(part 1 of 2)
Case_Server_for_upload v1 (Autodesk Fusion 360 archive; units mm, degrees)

design "Case_Server_for_upload" references "SSD1306_OLED_Display(128x64)", "DB_Updated", "Control"
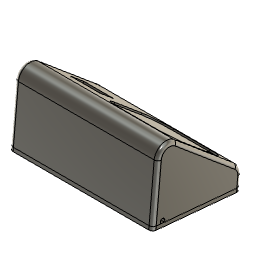
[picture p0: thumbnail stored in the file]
description: Part Number
part number: DB_Updated_PCB
external_derived "ExternalDerived1"
derived_instance "DerivedInstance1"
component_insert "Component Insert1"
sketch "Sketch1" plane through (0, 0, 0) normal (1, 0, 0) x axis (0, 1, 0)
  line L1 (0, 45.9198) -> (0, 0)
  line L2 (69.6996, 16.7708) -> (15.6902, 54.1431)
  line L3 (74.0094, 0) -> (74.0094, 8.5476)
  line L4 (0, 0) -> (74.0094, 0)
  line L5 (0, 4) -> (4, 4)
  line L6 (70.0094, 0) -> (70.0094, 4)
  line L7 (4, 0) -> (4, 4)
  line L8 (4, 45.9198) -> (4, 4)
  line L9 (67.4235, 13.4815) -> (13.4141, 50.8538)
  line L10 (70.0094, 4) -> (70.0094, 8.5476)
  line L11 (4, 4) -> (70.0094, 4)
  arc A1 centre (10, 45.9198) radius 10 clockwise from (0, 45.9198) to (15.6902, 54.1431)
  arc A2 centre (64.0094, 8.5476) radius 10 clockwise from (69.6996, 16.7708) to (74.0094, 8.5476)
  arc A3 centre (10, 45.9198) radius 6 clockwise from (4, 45.9198) to (13.4141, 50.8538)
  arc A4 centre (64.0094, 8.5476) radius 6 clockwise from (67.4235, 13.4815) to (70.0094, 8.5476)
  point P1 (0, 0)
  point P2 (0, 0)
  point P6 (0, 0)
  point P3 (0, 65)
  point P4 (74.0094, 13.7886)
  point P18 (0, 4)
  point P19 (70.0094, 0)
  point P20 (4, 0)
  coincident P1 P2
  vertical L1
  vertical L3
  coincident P1 P6
  perpendicular L1 L4
  coincident P3 L1
  coincident P3 L2
  tangent L1 A1
  tangent L2 A1
  coincident P4 L2
  coincident P4 L3
  tangent L2 A2
  tangent L3 A2
  equal A1 A2
  coincident L1 P18
  perpendicular L1 L5
  coincident L4 P19
  perpendicular L4 L6
  coincident L4 P20
  perpendicular L4 L7
  dimension "d1" distance P2 P3 = 65
  dimension "d2" distance P3 P4 = 90
  dimension "d3" radius A1 = 10
  dimension "d4" = 4
extrude "Extrude1" new body sketch "Sketch1" along normal blind 120
move "Move1"
shell "Shell1" innerThickness 5
fillet "Fillet1" radius 3
fillet "Fillet2" radius 3
sketch "Sketch2" plane through (0, 0, 0) normal (-1, 0, 0) x axis (0, -1, 0)
  line L1 (-3, 45.9198) -> (-3, 0)
  line L2 (-67.9925, 14.3039) -> (-13.9831, 51.6761)
  line L3 (-71.0094, 0) -> (-71.0094, 8.5476)
  line L4 (-3, 0) -> (-71.0094, 0)
  arc A1 centre (-10, 45.9198) radius 7 clockwise from (-13.9831, 51.6761) to (-3, 45.9198)
  arc A2 centre (-64.0094, 8.5476) radius 7 clockwise from (-71.0094, 8.5476) to (-67.9925, 14.3039)
  circle C1 centre (-9.0686, 10.0646) radius 3.15
  dimension "d12" diameter C1 = 6.3
extrude "Extrude2" cut sketch "Sketch2" profile of C1 against normal blind 5
sketch "Sketch3" plane through (120, 0, 0) normal (1, 0, 0) x axis (0, 1, 0)
  line L1 (71.0094, 8.5476) -> (71.0094, 0)
  line L2 (13.9831, 51.6761) -> (67.9925, 14.3039)
  line L3 (3, 0) -> (3, 45.9198)
  line L4 (71.0094, 0) -> (3, 0)
  line L5 (6.5581, 1.8971) -> (6.5581, 0)
  line L6 (6.5581, 0) -> (6.5581, 1.8971)
  line L7 (10.0566, 0) -> (10.0566, 1.8226)
  arc A1 centre (64.0094, 8.5476) radius 7 clockwise from (67.9925, 14.3039) to (71.0094, 8.5476)
  arc A2 centre (10, 45.9198) radius 7 clockwise from (3, 45.9198) to (13.9831, 51.6761)
  circle C1 centre (8.3081, 1.75) radius 1.75
  point P10 (6.5581, 0)
  point P13 (10.0566, 1.8226)
  point P14 (10.0566, 0)
  coincident L4 P10
  perpendicular L4 L5
  tangent L5 C1
  tangent L4 C1
  coincident C1 P13
  coincident L4 P14
  perpendicular L4 L7
  dimension "d16" radius C1 = 1.75
extrude "Extrude3" cut sketch "Sketch3" profile of L4 C1 L6 L7 against normal blind 5
sketch "Sketch4" plane through (0, 30.4146, 43.9544) normal (0, 0.569, 0.8223) x axis (-1, 0, 0)
  line L1 (-117, -47.773) -> (-117, 17.9058)
  line L2 (-3, -47.773) -> (-117, -47.773)
  line L3 (-3, 17.9058) -> (-3, -47.773)
  line L4 (-117, 17.9058) -> (-3, 17.9058)
  line L5 (-113.9567, 15.0558) -> (-113.9567, 17.9058)
  line L6 (-68.7567, 15.0558) -> (-98.9567, 15.0558)
  line L7 (-53.7567, -30.1442) -> (-53.7567, 0.0558)
  line L8 (-98.9567, -45.1442) -> (-68.7567, -45.1442)
  line L9 (-113.9567, 0.0558) -> (-113.9567, -30.1442)
  arc A1 centre (-68.7567, -30.1442) radius 15 clockwise from (-53.7567, -30.1442) to (-68.7567, -45.1442)
  arc A2 centre (-68.7567, 0.0558) radius 15 clockwise from (-68.7567, 15.0558) to (-53.7567, 0.0558)
  arc A3 centre (-98.9567, 0.0558) radius 15 clockwise from (-113.9567, 0.0558) to (-98.9567, 15.0558)
  arc A4 centre (-98.9567, -30.1442) radius 15 clockwise from (-98.9567, -45.1442) to (-113.9567, -30.1442)
  point P6 (-113.9567, 17.9058)
  point P8 (-53.7567, 15.0558)
  point P7 (-113.9567, 15.0558)
  point P9 (-113.9567, -45.1442)
  coincident L4 P6
  perpendicular L4 L5
  horizontal L6
  vertical L7
  horizontal L8
  vertical L9
  tangent L7 A1
  tangent L8 A1
  coincident P8 L6
  coincident P8 L7
  tangent L6 A2
  tangent L7 A2
  coincident P7 L9
  coincident P7 L6
  tangent L9 A3
  tangent L6 A3
  coincident P9 L9
  coincident P9 L8
  tangent L9 A4
  tangent L8 A4
  dimension "d19" distance P6 P7 = 2.85
  dimension "d20" distance P7 P8 = 60.2
  dimension "d21" distance P7 P9 = 60.2
  dimension "d22" radius A1 = 15
  dimension "d23" radius A2 = 15
  dimension "d24" radius A3 = 15
  dimension "d25" radius A4 = 15
extrude "Extrude4" cut sketch "Sketch4" profile of L6 L7 L8 L9 A1 A2 A3 A4 against normal blind 1.2
sketch "Sketch5" plane through (0, 30.4146, 43.9544) normal (0, 0.569, 0.8223) x axis (-1, 0, 0)
  line L1 (-113.9567, 0.0558) -> (-113.9567, -30.1442)
  line L2 (-68.7567, 15.0558) -> (-98.9567, 15.0558)
  line L3 (-53.7567, -30.1442) -> (-53.7567, 0.0558)
  line L4 (-98.9567, -45.1442) -> (-68.7567, -45.1442)
  line L5 (-117, -47.773) -> (-117, 17.9058)
  line L6 (-3, -47.773) -> (-117, -47.773)
  line L7 (-3, 17.9058) -> (-3, -47.773)
  line L8 (-117, 17.9058) -> (-3, 17.9058)
  line L9 (-3, -12.826) -> (-53.7567, -12.826)
  line L10 (-28.9783, -47.773) -> (-28.9783, 17.9058)
  line L11 (-40.7783, -21.176) -> (-15.9783, -21.176)
  line L12 (-40.7783, -4.476) -> (-40.7783, -21.176)
  line L13 (-15.9783, -4.476) -> (-40.7783, -4.476)
  line L14 (-15.9783, -21.176) -> (-15.9783, -4.476)
  line L15 (-40.7783, -4.476) -> (-15.9783, -21.176)
  line L16 (-15.9783, -4.476) -> (-40.7783, -21.176)
  line L17 (-41.4783, -25.926) -> (-15.2783, -25.926)
  line L18 (-41.4783, 0.274) -> (-41.4783, -25.926)
  line L19 (-15.2783, 0.274) -> (-41.4783, 0.274)
  line L20 (-15.2783, -25.926) -> (-15.2783, 0.274)
  line L21 (-41.4783, 0.274) -> (-15.2783, -25.926)
  line L22 (-15.2783, 0.274) -> (-41.4783, -25.926)
  arc A1 centre (-98.9567, 0.0558) radius 15 clockwise from (-113.9567, 0.0558) to (-98.9567, 15.0558)
  arc A2 centre (-68.7567, 0.0558) radius 15 clockwise from (-68.7567, 15.0558) to (-53.7567, 0.0558)
  arc A3 centre (-68.7567, -30.1442) radius 15 clockwise from (-53.7567, -30.1442) to (-68.7567, -45.1442)
  arc A4 centre (-98.9567, -30.1442) radius 15 clockwise from (-98.9567, -45.1442) to (-113.9567, -30.1442)
  point P18 (-53.7567, -12.826)
  point P19 (-3, -12.826)
  point P20 (-28.9783, 17.9058)
  point P21 (-28.9783, -47.773)
  point P26 (-28.3783, -12.826)
  point P31 (-28.3783, -12.826)
  point P24 (-40.7783, -4.476)
  point P25 (-15.9783, -4.476)
  point P23 (-40.7783, -21.176)
  point P29 (-41.4783, 0.274)
  point P30 (-15.2783, 0.274)
  point P28 (-41.4783, -25.926)
  coincident L3 P18
  coincident L7 P19
  perpendicular L7 L9
  coincident L8 P20
  coincident L6 P21
  perpendicular L6 L10
  horizontal L11
  perpendicular L11 L12
  parallel L11 L13
  parallel L12 L14
  coincident L15 P26
  coincident L16 P26
  midpoint L9 P26
  horizontal L17
  perpendicular L17 L18
  parallel L17 L19
  parallel L18 L20
  coincident L21 P31
  coincident L22 P31
  coincident P26 P31
  dimension "d28" distance P24 P25 = 24.8
  dimension "d29" distance P23 P24 = 16.7
  dimension "d30" distance P29 P30 = 26.2
  dimension "d31" distance P28 P29 = 26.2
sketch "Sketch6" plane through (0, 30.4146, 43.9544) normal (0, 0.569, 0.8223) x axis (-1, 0, 0)
  line L1 (-117, -47.773) -> (-117, 17.9058)
  line L2 (-3, -47.773) -> (-117, -47.773)
  line L3 (-3, 17.9058) -> (-3, -47.773)
  line L4 (-117, 17.9058) -> (-3, 17.9058)
  line L5 (-113.9567, 0.0558) -> (-113.9567, -30.1442)
  line L6 (-68.7567, 15.0558) -> (-98.9567, 15.0558)
  line L7 (-53.7567, -30.1442) -> (-53.7567, 0.0558)
  line L8 (-98.9567, -45.1442) -> (-68.7567, -45.1442)
  line L9 (-51.5262, 17.9058) -> (-117, 17.9058)
  line L10 (-51.5262, -47.773) -> (-51.5262, 17.9058)
  line L11 (-117, -47.773) -> (-51.5262, -47.773)
  line L12 (-117, 17.9058) -> (-117, -47.773)
  line L13 (-11.096, 0.5418) -> (-45.2906, 0.5418)
  line L14 (-11.096, -26.3669) -> (-11.096, 0.5418)
  line L15 (-45.2906, -26.3669) -> (-11.096, -26.3669)
  line L16 (-45.2906, 0.5418) -> (-45.2906, -26.3669)
  line L17 (-51.5262, 17.9058) -> (-117, 17.9058)
  line L18 (-51.5262, -47.773) -> (-51.5262, 17.9058)
  line L19 (-117, -47.773) -> (-51.5262, -47.773)
  line L20 (-117, 17.9058) -> (-117, -47.773)
  arc A1 centre (-98.9567, 0.0558) radius 15 clockwise from (-113.9567, 0.0558) to (-98.9567, 15.0558)
  arc A2 centre (-68.7567, 0.0558) radius 15 clockwise from (-68.7567, 15.0558) to (-53.7567, 0.0558)
  arc A3 centre (-68.7567, -30.1442) radius 15 clockwise from (-53.7567, -30.1442) to (-68.7567, -45.1442)
  arc A4 centre (-98.9567, -30.1442) radius 15 clockwise from (-98.9567, -45.1442) to (-113.9567, -30.1442)
  point P20 (-51.5262, -47.773)
  point P2 (-117, 17.9058)
  point P18 (-117, 17.9058)
  horizontal L9
  vertical L10
  horizontal L11
  vertical L12
  coincident L2 P20
  coincident P2 P18
  horizontal L13
  vertical L14
  horizontal L15
  vertical L16
  horizontal L17
  vertical L18
  horizontal L19
  vertical L20
sketch "Sketch7" plane through (0, 0, 0) normal (0, 0, 1) x axis (1, 0, 0)
  line L1 (-65.2, -35) -> (-35, -35)
  line L2 (-80.2, 10.2) -> (-80.2, -20)
  line L3 (-35, 25.2) -> (-65.2, 25.2)
  line L4 (-20, -20) -> (-20, 10.2)
  line L5 (-83.2, 10.2) -> (-83.2, -20)
  line L6 (-65.2, -38) -> (-35, -38)
  line L7 (-17, -20) -> (-17, 10.2)
  line L8 (-35, 28.2) -> (-65.2, 28.2)
  arc A1 centre (-35, -20) radius 15 clockwise from (-20, -20) to (-35, -35)
  arc A2 centre (-35, 10.2) radius 15 clockwise from (-35, 25.2) to (-20, 10.2)
  arc A3 centre (-65.2, -20) radius 15 clockwise from (-65.2, -35) to (-80.2, -20)
  arc A4 centre (-65.2, 10.2) radius 15 clockwise from (-80.2, 10.2) to (-65.2, 25.2)
  arc A5 centre (-65.2, 10.2) radius 18 clockwise from (-83.2, 10.2) to (-65.2, 28.2)
  arc A6 centre (-65.2, -20) radius 18 clockwise from (-65.2, -38) to (-83.2, -20)
  arc A7 centre (-35, -20) radius 18 clockwise from (-17, -20) to (-35, -38)
  arc A8 centre (-35, 10.2) radius 18 clockwise from (-35, 28.2) to (-17, 10.2)
  point P2 (-20, -35)
  point P4 (-20, 25.2)
  point P3 (-80.2, -35)
  horizontal L1
  vertical L2
  horizontal L3
  vertical L4
  coincident P2 L4
  coincident P2 L1
  tangent L4 A1
  tangent L1 A1
  coincident P4 L4
  coincident P4 L3
  tangent L4 A2
  tangent L3 A2
  coincident P3 L2
  coincident P3 L1
  tangent L2 A3
  tangent L1 A3
  tangent L2 A4
  tangent L3 A4
  dimension "d45" distance P2 P3 = 60.2
  dimension "d46" distance P2 P4 = 60.2
  dimension "d47" radius A1 = 15
  dimension "d48" radius A2 = 15
  dimension "d49" radius A3 = 15
  dimension "d50" radius A4 = 15
  dimension "d51" = -3
extrude "Extrude9" new body sketch "Sketch7" against normal blind 5
extrude "Extrude10" cut sketch "Sketch7" profile of L1 L2 L3 L4 A1 A2 A3 A4 against normal blind 1.3
sketch "Sketch8" plane through (0, 0, 0) normal (0, 0, -1) x axis (1, 0, 0)
  line L1 (120, -6.5581) -> (115, -6.5581)
  line L2 (120, -3) -> (120, -6.5581)
  line L3 (3, 0) -> (117, 0)
  line L4 (0, -71.0094) -> (0, -3)
  line L5 (117, -74.0094) -> (3, -74.0094)
  line L6 (120, -10.0566) -> (120, -71.0094)
  line L7 (115, -10.0566) -> (120, -10.0566)
  line L8 (115, -69.0094) -> (115, -10.0566)
  line L9 (5, -69.0094) -> (115, -69.0094)
  line L10 (5, -5) -> (5, -69.0094)
  line L11 (115, -5) -> (5, -5)
  line L12 (115, -6.5581) -> (115, -5)
  line L13 (115, -10.0566) -> (115, -6.5581)
  line L14 (120, -10.0566) -> (120, -6.5581)
  arc A1 centre (117, -3) radius 3 clockwise from (117, 0) to (120, -3)
  arc A2 centre (3, -3) radius 3 clockwise from (0, -3) to (3, 0)
  arc A3 centre (3, -71.0094) radius 3 clockwise from (3, -74.0094) to (0, -71.0094)
  arc A4 centre (117, -71.0094) radius 3 clockwise from (120, -71.0094) to (117, -74.0094)
  circle C1 centre (3, -3) radius 1.4
  circle C2 centre (117, -3) radius 1.4
  circle C3 centre (117, -71.0094) radius 1.4
  circle C4 centre (3, -71.0094) radius 1.4
  point P2 (115, -6.5581)
  point P22 (115, -6.5581)
  point P17 (115, -10.0566)
  point P23 (115, -10.0566)
  point P3 (120, -6.5581)
  point P24 (120, -6.5581)
  point P16 (120, -10.0566)
  point P25 (120, -10.0566)
  coincident P2 P22
  coincident P17 P23
  coincident P3 P24
  coincident P16 P25
  concentric A2 C1
  concentric A1 C2
  concentric A4 C3
  concentric A3 C4
  dimension "d59" diameter C1 = 2.8
  dimension "d99" diameter C2 = 2.8
  dimension "d100" diameter C3 = 2.8
  dimension "d101" diameter C4 = 2.8
move "Move2"
position "Position1"
sketch "Sketch1" plane through (0, 21.8322, 26.0187) normal (0, -0.6428, -0.766) x axis (1, 0, 0)
  line L1 (5, -47.773) -> (5, 17.9058)
  line L2 (115, -47.773) -> (5, -47.773)
  line L3 (115, 17.9058) -> (115, -47.773)
  line L4 (5, 17.9058) -> (115, 17.9058)
  line L5 (40.7783, -12.826) -> (15.9783, -12.826)
  line L6 (28.3783, -21.176) -> (28.3783, -12.826)
  point P8 (28.3783, -12.826)
  point P10 (28.3783, -12.826)
  point P11 (30.7776, -12.826)
  midpoint L5 P8
  coincident P8 P10
  coincident L5 P11
move "Move3"
move "Move4"
position "Position2"
sketch "Sketch2" plane through (0, 26.1389, 31.1512) normal (0, 0.6428, 0.766) x axis (-1, 0, 0)
  line L1 (-113.9567, 0.0558) -> (-113.9567, -30.1442)
  line L2 (-68.7567, 15.0558) -> (-98.9567, 15.0558)
  line L3 (-53.7567, -30.1442) -> (-53.7567, 0.0558)
  line L4 (-98.9567, -45.1442) -> (-68.7567, -45.1442)
  line L5 (-117, -47.773) -> (-117, 17.9058)
  line L6 (-3, -47.773) -> (-117, -47.773)
  line L7 (-3, 17.9058) -> (-3, -47.773)
  line L8 (-117, 17.9058) -> (-3, 17.9058)
  arc A1 centre (-98.9567, 0.0558) radius 15 clockwise from (-113.9567, 0.0558) to (-98.9567, 15.0558)
  arc A2 centre (-68.7567, 0.0558) radius 15 clockwise from (-68.7567, 15.0558) to (-53.7567, 0.0558)
  arc A3 centre (-68.7567, -30.1442) radius 15 clockwise from (-53.7567, -30.1442) to (-68.7567, -45.1442)
  arc A4 centre (-98.9567, -30.1442) radius 15 clockwise from (-98.9567, -45.1442) to (-113.9567, -30.1442)
move "Move5"
component_insert "Component Insert2"
position "Position3"
sketch "Sketch10" plane through (0, 30.4146, 43.9544) normal (0, 0.569, 0.8223) x axis (-1, 0, 0)
  line L1 (-113.9567, 0.0558) -> (-113.9567, -30.1442)
  line L2 (-68.7567, 15.0558) -> (-98.9567, 15.0558)
  line L3 (-53.7567, -30.1442) -> (-53.7567, 0.0558)
  line L4 (-98.9567, -45.1442) -> (-68.7567, -45.1442)
  line L5 (-117, -47.773) -> (-117, 17.9058)
  line L6 (-3, -47.773) -> (-117, -47.773)
  line L7 (-3, 17.9058) -> (-3, -47.773)
  line L8 (-117, 17.9058) -> (-3, 17.9058)
  line L9 (-30.6726, -2.6578) -> (-30.6726, -2.7517)
  line L10 (-30.3337, -2.6573) -> (-30.6726, -2.6578)
  line L11 (-30.3337, -2.9542) -> (-30.3337, -2.6573)
  curve K1 (-30.4947, -3.0478) -> (-30.3337, -2.9542)
  curve K2 (-30.6649, -3.0791) -> (-30.4947, -3.0478)
  curve K3 (-30.8791, -3.0287) -> (-30.6649, -3.0791)
  curve K4 (-31.0246, -2.8827) -> (-30.8791, -3.0287)
  curve K5 (-31.0737, -2.6693) -> (-31.0246, -2.8827)
  curve K6 (-31.0248, -2.4513) -> (-31.0737, -2.6693)
  curve K7 (-30.8843, -2.301) -> (-31.0248, -2.4513)
  curve K8 (-30.6731, -2.2518) -> (-30.8843, -2.301)
  curve K9 (-30.5162, -2.2799) -> (-30.6731, -2.2518)
  curve K10 (-30.4063, -2.3583) -> (-30.5162, -2.2799)
  curve K11 (-30.3457, -2.4892) -> (-30.4063, -2.3583)
  line L12 (-30.4412, -2.5154) -> (-30.3457, -2.4892)
  curve K12 (-30.4859, -2.4194) -> (-30.4412, -2.5154)
  curve K13 (-30.5623, -2.3634) -> (-30.4859, -2.4194)
  curve K14 (-30.6726, -2.3424) -> (-30.5623, -2.3634)
  curve K15 (-30.7981, -2.3645) -> (-30.6726, -2.3424)
  curve K16 (-30.8835, -2.4226) -> (-30.7981, -2.3645)
  curve K17 (-30.934, -2.5018) -> (-30.8835, -2.4226)
  curve K18 (-30.9645, -2.6628) -> (-30.934, -2.5018)
  curve K19 (-30.9277, -2.8417) -> (-30.9645, -2.6628)
  curve K20 (-30.8205, -2.9487) -> (-30.9277, -2.8417)
  curve K21 (-30.6709, -2.9836) -> (-30.8205, -2.9487)
  curve K22 (-30.5367, -2.9572) -> (-30.6709, -2.9836)
  curve K23 (-30.4374, -2.9007) -> (-30.5367, -2.9572)
  line L13 (-30.4374, -2.7517) -> (-30.4374, -2.9007)
  line L14 (-30.6726, -2.7517) -> (-30.4374, -2.7517)
  line L15 (-21.3678, -2.2655) -> (-21.675, -3.0655)
  line L16 (-21.2538, -2.2655) -> (-21.3678, -2.2655)
  line L17 (-20.9263, -3.0655) -> (-21.2538, -2.2655)
  line L18 (-21.0469, -3.0655) -> (-20.9263, -3.0655)
  line L19 (-21.1402, -2.8232) -> (-21.0469, -3.0655)
  line L20 (-21.4748, -2.8232) -> (-21.1402, -2.8232)
  line L21 (-21.5626, -3.0655) -> (-21.4748, -2.8232)
  line L22 (-21.675, -3.0655) -> (-21.5626, -3.0655)
  line L23 (-24.1607, -2.8117) -> (-24.2666, -2.785)
  curve K24 (-24.2805, -3.0106) -> (-24.1607, -2.8117)
  curve K25 (-24.492, -3.0791) -> (-24.2805, -3.0106)
  curve K26 (-24.7023, -3.0265) -> (-24.492, -3.0791)
  curve K27 (-24.8256, -2.8739) -> (-24.7023, -3.0265)
  curve K28 (-24.8679, -2.6595) -> (-24.8256, -2.8739)
  curve K29 (-24.8202, -2.4415) -> (-24.8679, -2.6595)
  curve K30 (-24.6843, -2.3001) -> (-24.8202, -2.4415)
  curve K31 (-24.4903, -2.2518) -> (-24.6843, -2.3001)
  curve K32 (-24.2884, -2.313) -> (-24.4903, -2.2518)
  curve K33 (-24.1744, -2.4849) -> (-24.2884, -2.313)
  line L24 (-24.2786, -2.5094) -> (-24.1744, -2.4849)
  curve K34 (-24.3593, -2.3823) -> (-24.2786, -2.5094)
  curve K35 (-24.4925, -2.3424) -> (-24.3593, -2.3823)
  curve K36 (-24.6467, -2.3866) -> (-24.4925, -2.3424)
  curve K37 (-24.7337, -2.5053) -> (-24.6467, -2.3866)
  curve K38 (-24.7588, -2.6589) -> (-24.7337, -2.5053)
  curve K39 (-24.7291, -2.8371) -> (-24.7588, -2.6589)
  curve K40 (-24.6366, -2.9509) -> (-24.7291, -2.8371)
  curve K41 (-24.5007, -2.9885) -> (-24.6366, -2.9509)
  curve K42 (-24.3501, -2.9372) -> (-24.5007, -2.9885)
  curve K43 (-24.2666, -2.785) -> (-24.3501, -2.9372)
  line L25 (-23.0759, -2.7997) -> (-23.1757, -2.8085)
  curve K44 (-23.0428, -2.8982) -> (-23.0759, -2.7997)
  curve K45 (-22.9623, -2.9604) -> (-23.0428, -2.8982)
  curve K46 (-22.8396, -2.9842) -> (-22.9623, -2.9604)
  curve K47 (-22.7326, -2.9662) -> (-22.8396, -2.9842)
  curve K48 (-22.6636, -2.9168) -> (-22.7326, -2.9662)
  curve K49 (-22.6409, -2.8483) -> (-22.6636, -2.9168)
  curve K50 (-22.6628, -2.7825) -> (-22.6409, -2.8483)
  curve K51 (-22.7348, -2.7353) -> (-22.6628, -2.7825)
  curve K52 (-22.8772, -2.6963) -> (-22.7348, -2.7353)
  curve K53 (-23.0317, -2.6464) -> (-22.8772, -2.6963)
  curve K54 (-23.1171, -2.5719) -> (-23.0317, -2.6464)
  curve K55 (-23.1452, -2.4723) -> (-23.1171, -2.5719)
  curve K56 (-23.1108, -2.3591) -> (-23.1452, -2.4723)
  curve K57 (-23.0104, -2.2791) -> (-23.1108, -2.3591)
  curve K58 (-22.8636, -2.2518) -> (-23.0104, -2.2791)
  curve K59 (-22.7067, -2.2805) -> (-22.8636, -2.2518)
  curve K60 (-22.6022, -2.3648) -> (-22.7067, -2.2805)
  curve K61 (-22.5629, -2.4909) -> (-22.6022, -2.3648)
  line L26 (-22.6644, -2.4985) -> (-22.5629, -2.4909)
  curve K62 (-22.7198, -2.3839) -> (-22.6644, -2.4985)
  curve K63 (-22.8592, -2.3452) -> (-22.7198, -2.3839)
  curve K64 (-22.9992, -2.3804) -> (-22.8592, -2.3452)
  curve K65 (-23.0431, -2.4652) -> (-22.9992, -2.3804)
  curve K66 (-23.012, -2.5362) -> (-23.0431, -2.4652)
  curve K67 (-22.8524, -2.5932) -> (-23.012, -2.5362)
  curve K68 (-22.6753, -2.6442) -> (-22.8524, -2.5932)
  curve K69 (-22.5722, -2.7258) -> (-22.6753, -2.6442)
  curve K70 (-22.5389, -2.8396) -> (-22.5722, -2.7258)
  curve K71 (-22.5754, -2.9599) -> (-22.5389, -2.8396)
  curve K72 (-22.6805, -3.0478) -> (-22.5754, -2.9599)
  curve K73 (-22.8347, -3.0791) -> (-22.6805, -3.0478)
  curve K74 (-23.0166, -3.0475) -> (-22.8347, -3.0791)
  curve K75 (-23.1318, -2.9523) -> (-23.0166, -3.0475)
  curve K76 (-23.1757, -2.8085) -> (-23.1318, -2.9523)
  line L27 (-33.3, -25.8655) -> (-38.7, -25.8655)
  line L28 (-33.3, -24.3655) -> (-33.3, -25.8655)
  line L29 (-19.7, -23.3655) -> (-32.3, -23.3655)
  line L30 (-18.7, -25.8655) -> (-18.7, -24.3655)
  line L31 (-13.3, -25.8655) -> (-18.7, -25.8655)
  line L32 (-13.3, 0.3345) -> (-13.3, -25.8655)
  line L33 (-38.7, 0.3345) -> (-13.3, 0.3345)
  line L34 (-38.7, -25.8655) -> (-38.7, 0.3345)
  line L35 (-30.1787, -2.2655) -> (-30.1787, -3.0655)
  line L36 (-30.0701, -2.2655) -> (-30.1787, -2.2655)
  line L37 (-29.6499, -2.8936) -> (-30.0701, -2.2655)
  line L38 (-29.6499, -2.2655) -> (-29.6499, -2.8936)
  line L39 (-29.5484, -2.2655) -> (-29.6499, -2.2655)
  line L40 (-29.5484, -3.0655) -> (-29.5484, -2.2655)
  line L41 (-29.657, -3.0655) -> (-29.5484, -3.0655)
  line L42 (-30.0772, -2.4368) -> (-29.657, -3.0655)
  line L43 (-30.0772, -3.0655) -> (-30.0772, -2.4368)
  line L44 (-30.1787, -3.0655) -> (-30.0772, -3.0655)
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  point P261 (-13.65, -18.6655)
  point P270 (-13.65, -18.6655)
  point P263 (-38.35, -4.1655)
  point P268 (-38.35, -4.1655)
  point P121 (-13.3, -25.8655)
  point P274 (-13.3, -25.8655)
  point P123 (-38.7, 0.3345)
  point P272 (-38.7, 0.3345)
  coincident P261 P270
  coincident P263 P268
  coincident P121 P274
  coincident P123 P272
  dimension "d81" diameter = 1.5
  dimension "d82" diameter = 1.5
  dimension "d83" diameter = 1.5
  dimension "d84" diameter = 1.5
  dimension "d87" = -0.1
extrude "Extrude16" cut sketch "Sketch10" along a picked direction blind -7
extrude "Extrude17" cut sketch "Sketch10" along a picked direction blind 1 from offset -5
sketch "Sketch11" plane through (5, 0, 0) normal (1, 0, 0) x axis (0, 1, 0)
  line L1 (69.0094, 8.5476) -> (69.0094, 0)
  line L2 (12.8451, 50.0314) -> (66.8545, 12.6592)
  line L3 (5, 0) -> (5, 45.9198)
  line L4 (69.0094, 0) -> (5, 0)
  circle C1 centre (9.0686, 10.0646) radius 3.15
  arc A1 centre (64.0094, 8.5476) radius 5 clockwise from (66.8545, 12.6592) to (69.0094, 8.5476)
  arc A2 centre (10, 45.9198) radius 5 clockwise from (5, 45.9198) to (12.8451, 50.0314)
  circle C2 centre (9.0686, 10.0646) radius 4.0627
  concentric C1 C2
extrude "Extrude19" add sketch "Sketch11" profile of C1 C2 along normal blind 3
extrude "Extrude20" cut sketch "Sketch10" along a picked direction blind 3 from offset -4
extrude "Extrude21" cut sketch "Sketch8" profile of C1 C2 C3 C4 along a picked direction blind -4
extrude "Extrude1" new body sketch "Sketch8" along normal blind 3
sketch "Sketch12" plane through (0, 0, -3) normal (0, 0, -1) x axis (1, 0, 0)
  line L1 (3, 0) -> (117, 0)
  line L2 (0, -71.0094) -> (0, -3)
  line L3 (117, -74.0094) -> (3, -74.0094)
  line L4 (120, -3) -> (120, -71.0094)
  circle C1 centre (117, -3) radius 1.4
  circle C2 centre (117, -71.0094) radius 1.4
  circle C3 centre (3, -3) radius 1.4
  circle C4 centre (3, -71.0094) radius 1.4
  arc A1 centre (117, -3) radius 3 clockwise from (117, 0) to (120, -3)
  arc A2 centre (3, -3) radius 3 clockwise from (0, -3) to (3, 0)
  arc A3 centre (3, -71.0094) radius 3 clockwise from (3, -74.0094) to (0, -71.0094)
  arc A4 centre (117, -71.0094) radius 3 clockwise from (120, -71.0094) to (117, -74.0094)
sketch "Sketch1" plane through (0, 0, -3) normal (0, 0, -1) x axis (1, 0, 0)
  line L1 (3, 0) -> (117, 0)
  line L2 (0, -71.0094) -> (0, -3)
  line L3 (117, -74.0094) -> (3, -74.0094)
  line L4 (120, -3) -> (120, -71.0094)
  line L5 (120, -6.5581) -> (115, -6.5581)
  line L6 (120, -3) -> (120, -6.5581)
  line L7 (3, 0) -> (117, 0)
  line L8 (0, -71.0094) -> (0, -3)
  line L9 (117, -74.0094) -> (3, -74.0094)
  line L10 (120, -10.0566) -> (120, -71.0094)
  line L11 (115, -10.0566) -> (120, -10.0566)
  line L12 (115, -69.0094) -> (115, -10.0566)
  line L13 (5, -69.0094) -> (115, -69.0094)
  line L14 (5, -5) -> (5, -69.0094)
  line L15 (115, -5) -> (5, -5)
  line L16 (115, -6.5581) -> (115, -5)
  line L17 (5, -69.0094) -> (115, -69.0094)
  line L18 (5, -5) -> (5, -69.0094)
  line L19 (115, -5) -> (5, -5)
  line L20 (115, -69.0094) -> (115, -5)
  line L21 (114.7, -5.3) -> (5.3, -5.3)
  line L22 (114.7, -68.7094) -> (114.7, -5.3)
  line L23 (5.3, -68.7094) -> (114.7, -68.7094)
  line L24 (5.3, -5.3) -> (5.3, -68.7094)
  circle C1 centre (117, -3) radius 1.4
  circle C2 centre (117, -71.0094) radius 1.4
  circle C3 centre (3, -3) radius 1.4
  circle C4 centre (3, -71.0094) radius 1.4
  arc A1 centre (117, -3) radius 3 clockwise from (117, 0) to (120, -3)
  arc A2 centre (3, -3) radius 3 clockwise from (0, -3) to (3, 0)
  arc A3 centre (3, -71.0094) radius 3 clockwise from (3, -74.0094) to (0, -71.0094)
  arc A4 centre (117, -71.0094) radius 3 clockwise from (120, -71.0094) to (117, -74.0094)
  circle C5 centre (3, -71.0094) radius 1.4
  circle C6 centre (117, -3) radius 1.4
  circle C7 centre (117, -71.0094) radius 1.4
  circle C8 centre (3, -3) radius 1.4
  arc A5 centre (117, -3) radius 3 clockwise from (117, 0) to (120, -3)
  arc A6 centre (3, -3) radius 3 clockwise from (0, -3) to (3, 0)
  arc A7 centre (3, -71.0094) radius 3 clockwise from (3, -74.0094) to (0, -71.0094)
  arc A8 centre (117, -71.0094) radius 3 clockwise from (120, -71.0094) to (117, -74.0094)
  point P32 (5, -5)
  point P36 (5, -5)
  point P30 (115, -69.0094)
  point P34 (115, -69.0094)
  horizontal L17
  vertical L18
  horizontal L19
  vertical L20
  coincident P32 P36
  coincident P30 P34
  dimension "d106" = 0.3
extrude "Extrude2" add sketch "Sketch1" profile of L22 L24 L23 L21 along a picked direction blind -2 from offset -3
remove_body "RemoveBody1"
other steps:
derived_base_feature "Derived Base Feature1"
derived_base_feature "Derived Base Feature1"
derived_base_feature "Derived Base Feature2"
create_component "CreateComponent1"
create_component "CreateComponent2"
create_component "CreateComponent1"
named bodies: "Case"

design "SSD1306_OLED_Display(128x64)"
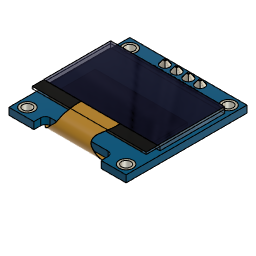
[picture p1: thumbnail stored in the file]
sketch "Sketch1" plane through (0, 0, 0) normal (0, 0, 1) x axis (1, 0, 0)
  line L1 (-12.7, -13.1) -> (12.7, -13.1)
  line L2 (-12.7, 13.1) -> (-12.7, -13.1)
  line L3 (12.7, 13.1) -> (-12.7, 13.1)
  line L4 (12.7, -13.1) -> (12.7, 13.1)
  line L5 (-12.7, 13.1) -> (12.7, -13.1)
  line L6 (12.7, 13.1) -> (-12.7, -13.1)
  line L7 (-12.7, 13.1) -> (-12.7, -13.1)
  line L8 (12.7, 13.1) -> (-12.7, 13.1)
  line L9 (12.7, -13.1) -> (12.7, 13.1)
  line L10 (7.3, -13.1) -> (12.7, -13.1)
  line L11 (7.3, -10.6) -> (7.3, -13.1)
  line L12 (-7.3, -10.6) -> (7.3, -10.6)
  line L13 (-7.3, -13.1) -> (-12.7, -13.1)
  line L14 (-7.3, -10.6) -> (-7.3, -13.1)
  line L15 (0, -10.6) -> (0, 13.1)
  line L16 (12.7, 0) -> (-12.7, 0)
  circle C1 centre (-10.7, 11.1) radius 1
  circle C2 centre (-10.7, 11.1) radius 1.5
  circle C3 centre (10.7, 11.1) radius 1.5
  circle C4 centre (10.7, 11.1) radius 1
  circle C5 centre (-10.7, -11.1) radius 1.5
  circle C6 centre (-10.7, -11.1) radius 1
  circle C7 centre (10.7, -11.1) radius 1.5
  circle C8 centre (10.7, -11.1) radius 1
  point P6 (0, 0)
  point P1 (0, 0)
  point P7 (7.3, -13.1)
  point P10 (-7.3, -13.1)
  point P11 (0, 13.1)
  point P12 (0, -10.6)
  point P17 (-12.7, 0)
  point P18 (12.7, 0)
  point P4 (-12.7, 13.1)
  point P5 (12.7, 13.1)
  point P3 (-12.7, -13.1)
  point P8 (7.3, -10.6)
  point P9 (-7.3, -10.6)
  point P13 (-10.7, 11.1)
  horizontal L1
  perpendicular L1 L2
  parallel L1 L3
  parallel L2 L4
  coincident L5 P6
  coincident L6 P6
  coincident P1 P6
  coincident L1 P7
  perpendicular L10 L11
  perpendicular L11 L12
  coincident L1 P10
  perpendicular L12 L14
  midpoint L3 P11
  midpoint L12 P12
  vertical L15
  symmetric L15 C1 C4
  symmetric L15 C2 C3
  midpoint L2 P17
  midpoint L9 P18
  symmetric C1 L16 C6
  symmetric C2 L16 C5
  symmetric C3 L16 C7
  symmetric C4 L16 C8
  dimension "d1" distance P4 P5 = 25.4
  dimension "d2" distance P3 P4 = 26.2
  dimension "d3" distance P8 P9 = 14.6
  dimension "d4" distance L1 L12 = 2.5
  dimension "d5" diameter C1 = 2
  dimension "d6" distance L7 P13 = 2
  dimension "d7" distance L3 P13 = 2
  dimension "d8" = 0.5
extrude "Extrude1" new body sketch "Sketch1" profile of L7 L8 L9 L10 L11 L12 L13 L14 C2 C3 C5 C7 along normal blind 1.5
extrude "Extrude2" new body sketch "Sketch1" profile of C1 C2 C3 C4 C5 C6 C7 C8 along normal blind 1.5 bodies "ring2", "ring3", "ring1", "ring4"
fillet "Fillet1" radius 1 1
ground "Ground1"
sketch "Sketch1" plane through (0, 0, 1.5) normal (0, 0, 1) x axis (-1, 0, 0)
  line L1 (7.3, 13.1) -> (12.7, 13.1)
  line L2 (7.3, 11.6) -> (7.3, 13.1)
  line L3 (-6.3, 10.6) -> (6.3, 10.6)
  line L4 (-7.3, 13.1) -> (-7.3, 11.6)
  line L5 (-12.7, 13.1) -> (-7.3, 13.1)
  line L6 (-12.7, -13.1) -> (-12.7, 13.1)
  line L7 (12.7, -13.1) -> (-12.7, -13.1)
  line L8 (12.7, 13.1) -> (12.7, -13.1)
  line L9 (0, 10.6) -> (0, -13.1)
  line L10 (-12.7, 0) -> (12.7, 0)
  line L11 (10, 7.1) -> (-10, 7.1)
  line L12 (10, -2.9) -> (10, 7.1)
  line L13 (-10, -2.9) -> (10, -2.9)
  line L14 (-10, 7.1) -> (-10, -2.9)
  line L15 (10, -2.9) -> (-10, 7.1)
  line L16 (-10, -2.9) -> (10, 7.1)
  circle C1 centre (10.7, -11.1) radius 1.5
  circle C2 centre (-10.7, -11.1) radius 1.5
  circle C3 centre (10.7, 11.1) radius 1.5
  circle C4 centre (-10.7, 11.1) radius 1.5
  arc A1 centre (6.3, 11.6) radius 1 clockwise from (7.3, 11.6) to (6.3, 10.6)
  arc A2 centre (-6.3, 11.6) radius 1 clockwise from (-6.3, 10.6) to (-7.3, 11.6)
  point P18 (0, -13.1)
  point P19 (0, 10.6)
  point P20 (12.7, 0)
  point P21 (-12.7, 0)
  point P26 (0, 2.1)
  point P24 (10, -2.9)
  point P25 (-10, -2.9)
  point P23 (10, 7.1)
  midpoint L7 P18
  midpoint L3 P19
  midpoint L8 P20
  midpoint L6 P21
  horizontal L11
  perpendicular L11 L12
  parallel L11 L13
  parallel L12 L14
  coincident L15 P26
  coincident L16 P26
  coincident L9 P26
  dimension "d17" distance P24 P25 = 20
  dimension "d18" distance P23 P24 = 10
  dimension "d19" distance L1 L11 = 6
extrude "Extrude1" new body sketch "Sketch1" profile of L11 L12 L13 L14 along normal blind 0.5 bodies "pad"
sketch "Sketch2" plane through (0, 0, 2) normal (0, 0, 1) x axis (-1, 0, 0)
  line L1 (10, -2.9) -> (-10, -2.9)
  line L2 (10, 7.1) -> (10, -2.9)
  line L3 (-10, 7.1) -> (10, 7.1)
  line L4 (-10, -2.9) -> (-10, 7.1)
  line L5 (0, 10.6) -> (0, -13.1)
  line L6 (-12.7, 0) -> (12.7, 0)
  line L7 (12.7, 13.1) -> (12.7, -13.1)
  line L8 (-12.7, -13.1) -> (-12.7, 13.1)
  line L9 (12.7, -13.1) -> (-12.7, -13.1)
  line L10 (-12.7, 13.1) -> (-7.3, 13.1)
  line L11 (-6.3, 10.6) -> (6.3, 10.6)
  line L12 (12.35, 5.4) -> (-12.35, 5.4)
  line L13 (12.35, -8.6) -> (12.35, 5.4)
  line L14 (-12.35, -8.6) -> (12.35, -8.6)
  line L15 (-12.35, 5.4) -> (-12.35, -8.6)
  line L16 (12.35, -8.6) -> (-12.35, 5.4)
  line L17 (-12.35, -8.6) -> (12.35, 5.4)
  point P9 (-12.7, 0)
  point P8 (12.7, 0)
  point P6 (0, -13.1)
  point P7 (0, 10.6)
  point P21 (0, -1.6)
  point P19 (12.35, -8.6)
  point P20 (-12.35, -8.6)
  point P18 (12.35, 5.4)
  perpendicular L1 L5
  perpendicular L4 L6
  symmetric L5 L7 L8
  coincident P9 L8
  coincident P8 L7
  coincident P6 L9
  coincident P7 L11
  horizontal L12
  perpendicular L12 L13
  parallel L12 L14
  parallel L13 L15
  coincident L16 P21
  coincident L17 P21
  coincident L5 P21
  dimension "d22" distance P19 P20 = 24.7
  dimension "d23" distance P18 P19 = 14
  dimension "d24" distance L9 L14 = 4.5
extrude "Extrude2" new body sketch "Sketch2" profile of L1 L2 L4 L12 L13 L14 L15 along normal blind 0.8 bodies "glass1"
sketch "Sketch3" plane through (0, 0, 2.8) normal (0, 0, 1) x axis (-1, 0, 0)
  line L1 (12.35, -8.6) -> (-12.35, -8.6)
  line L2 (12.35, 5.4) -> (12.35, -8.6)
  line L3 (-12.35, 5.4) -> (12.35, 5.4)
  line L4 (-12.35, -8.6) -> (-12.35, 5.4)
  line L5 (-12.35, -8.6) -> (12.35, -8.6)
  line L6 (-12.35, 8.4) -> (-12.35, -8.6)
  line L7 (12.35, 8.4) -> (-12.35, 8.4)
  line L8 (12.35, -8.6) -> (12.35, 8.4)
  point P3 (12.35, -8.6)
  point P6 (12.35, -8.6)
  point P9 (12.35, 8.4)
  horizontal L5
  vertical L6
  horizontal L7
  vertical L8
  coincident P3 P6
  dimension "d27" distance P6 P9 = 17
extrude "Extrude3" new body sketch "Sketch3" along normal blind 0.5 bodies "glass2"
sketch "Sketch4" plane through (-12.35, 0, 0) normal (-1, 0, 0) x axis (0, -1, 0)
  line L1 (8.4, 2.8) -> (-8.6, 2.8)
  line L2 (8.4, 3.3) -> (8.4, 2.8)
  line L3 (-8.6, 3.3) -> (8.4, 3.3)
  line L4 (-8.6, 2.8) -> (-8.6, 3.3)
  line L5 (5.9, 3.3) -> (8.4, 3.3)
  line L6 (5.9, 3.25) -> (5.9, 3.3)
  line L7 (8.4, 3.25) -> (5.9, 3.25)
  line L8 (8.4, 3.3) -> (8.4, 3.25)
  point P4 (8.4, 3.3)
  point P6 (8.4, 3.3)
  point P7 (5.9, 3.3)
  point P9 (8.4, 3.25)
  horizontal L5
  vertical L6
  horizontal L7
  vertical L8
  coincident P4 P6
  dimension "d30" distance P6 P7 = 2.5
  dimension "d31" distance P6 P9 = 0.05
extrude "Extrude4" cut sketch "Sketch4" profile of L2 L3 L5 L6 L7 L8 no distance stored
sketch "Sketch1" plane through (0, 0, 0) normal (0, 0, -1) x axis (1, 0, 0)
  line L1 (-12.7, 13.1) -> (-7.3, 13.1)
  line L2 (-12.7, -13.1) -> (-12.7, 13.1)
  line L3 (12.7, -13.1) -> (-12.7, -13.1)
  line L4 (12.7, 13.1) -> (12.7, -13.1)
  line L5 (7.3, 13.1) -> (12.7, 13.1)
  line L6 (7.3, 11.6) -> (7.3, 13.1)
  line L7 (-6.3, 10.6) -> (6.3, 10.6)
  line L8 (-7.3, 13.1) -> (-7.3, 11.6)
  line L9 (0, 10.6) -> (0, -13.1)
  line L10 (5.08, -13.1) -> (-5.08, -13.1)
  line L11 (5.08, -10.56) -> (5.08, -13.1)
  line L12 (-5.08, -10.56) -> (5.08, -10.56)
  line L13 (-5.08, -13.1) -> (-5.08, -10.56)
  line L14 (5.08, -10.56) -> (-5.08, -13.1)
  line L15 (-5.08, -10.56) -> (5.08, -13.1)
  line L16 (2.54, -10.56) -> (2.54, -13.1)
  line L17 (2.54, -13.1) -> (5.08, -13.1)
  line L18 (2.54, -10.56) -> (2.54, -13.1)
  line L19 (5.08, -10.56) -> (2.54, -10.56)
  line L20 (5.08, -13.1) -> (5.08, -10.56)
  circle C1 centre (-10.7, -11.1) radius 1.5
  circle C2 centre (10.7, -11.1) radius 1.5
  circle C3 centre (-10.7, 11.1) radius 1.5
  circle C4 centre (10.7, 11.1) radius 1.5
  arc A1 centre (6.3, 11.6) radius 1 clockwise from (7.3, 11.6) to (6.3, 10.6)
  arc A2 centre (-6.3, 11.6) radius 1 clockwise from (-6.3, 10.6) to (-7.3, 11.6)
  point P18 (0, -13.1)
  point P19 (0, 10.6)
  point P20 (-5.08, -13.1)
  point P24 (0, -11.83)
  point P25 (2.54, -13.1)
  point P26 (2.54, -10.56)
  point P21 (5.08, -13.1)
  point P23 (-5.08, -10.56)
  midpoint L3 P18
  midpoint L7 P19
  horizontal L10
  perpendicular L10 L11
  parallel L10 L12
  parallel L11 L13
  coincident L3 P20
  coincident L14 P24
  coincident L15 P24
  coincident L9 P24
  coincident L10 P25
  coincident L12 P26
  perpendicular L12 L16
  horizontal L17
  vertical L18
  horizontal L19
  vertical L20
  dimension "d33" distance P20 P21 = 10.16 (= "( 2.54 * 4 ) * 1 mm")
  dimension "d34" distance P20 P23 = 2.54
  dimension "d35" distance L11 L16 = 2.54
extrude "Extrude1" new body sketch "Sketch1" profile of L3 L17 L18 L19 L20 along normal blind 2.5 bodies "header1"
chamfer "Chamfer1" distance 0.5
chamfer "Chamfer2" distance 0.5 distance 0.5 distance 0.5
sketch "Sketch2" plane through (0, 0, -2.5) normal (0, 0, -1) x axis (1, 0, 0)
  line L1 (5.08, -12.6) -> (4.58, -13.1)
  line L2 (5.08, -11.06) -> (5.08, -12.6)
  line L3 (4.58, -10.56) -> (5.08, -11.06)
  line L4 (3.04, -10.56) -> (4.58, -10.56)
  line L5 (2.54, -11.06) -> (3.04, -10.56)
  line L6 (2.54, -12.6) -> (2.54, -11.06)
  line L7 (3.04, -13.1) -> (2.54, -12.6)
  line L8 (4.58, -13.1) -> (3.04, -13.1)
  line L9 (3.81, -13.1) -> (3.81, -10.56)
  line L10 (5.08, -11.83) -> (2.54, -11.83)
  line L11 (3.56, -12.08) -> (4.06, -12.08)
  line L12 (3.56, -11.58) -> (3.56, -12.08)
  line L13 (4.06, -11.58) -> (3.56, -11.58)
  line L14 (4.06, -12.08) -> (4.06, -11.58)
  line L15 (3.56, -11.58) -> (4.06, -12.08)
  line L16 (4.06, -11.58) -> (3.56, -12.08)
  point P10 (3.81, -10.56)
  point P11 (3.81, -13.1)
  point P12 (2.54, -11.83)
  point P13 (5.08, -11.83)
  point P18 (3.81, -11.83)
  point P16 (3.56, -11.58)
  point P17 (4.06, -11.58)
  point P15 (3.56, -12.08)
  midpoint L4 P10
  midpoint L8 P11
  midpoint L6 P12
  midpoint L2 P13
  horizontal L11
  perpendicular L11 L12
  parallel L11 L13
  parallel L12 L14
  coincident L15 P18
  coincident L16 P18
  midpoint L10 P18
  dimension "d42" distance P16 P17 = 0.5
  dimension "d43" distance P15 P16 = 0.5
extrude "Extrude2" cut sketch "Sketch2" profile of L11 L12 L13 L14 against normal blind 3.6
extrude "Extrude3" new body sketch "Sketch2" profile of L11 L12 L13 L14 blind -11 from offset 6 bodies "pin1"
chamfer "Chamfer3" distance 0.1 distance 0.1
rectangular_pattern "R-Pattern1" uSpaceDistance 2.54 vSpaceDistance 0 bodies "header2", "header3", "header4", "pin2", "pin3", "pin4 (1)"
sketch "Sketch2" plane through (0, 0, 1.5) normal (0, 0, 1) x axis (-1, 0, 0)
  line L1 (7.3, 13.1) -> (12.7, 13.1)
  line L2 (7.3, 11.6) -> (7.3, 13.1)
  line L3 (-6.3, 10.6) -> (6.3, 10.6)
  line L4 (-7.3, 13.1) -> (-7.3, 11.6)
  line L5 (-12.7, 13.1) -> (-7.3, 13.1)
  line L6 (-12.7, -13.1) -> (-12.7, 13.1)
  line L7 (12.7, -13.1) -> (-12.7, -13.1)
  line L8 (12.7, 13.1) -> (12.7, -13.1)
  line L9 (3.81, -11.68) -> (3.81, -11.98)
  line L10 (3.96, -11.83) -> (3.66, -11.83)
  line L11 (3.66, -11.98) -> (3.96, -11.98)
  line L12 (3.96, -11.68) -> (3.66, -11.68)
  line L13 (3.96, -11.98) -> (3.96, -11.68)
  line L14 (3.66, -11.68) -> (3.66, -11.98)
  circle C1 centre (10.7, -11.1) radius 1.5
  circle C2 centre (-10.7, -11.1) radius 1.5
  circle C3 centre (10.7, 11.1) radius 1.5
  circle C4 centre (-10.7, 11.1) radius 1.5
  arc A1 centre (6.3, 11.6) radius 1 clockwise from (7.3, 11.6) to (6.3, 10.6)
  arc A2 centre (-6.3, 11.6) radius 1 clockwise from (-6.3, 10.6) to (-7.3, 11.6)
  circle C5 centre (3.81, -11.83) radius 0.5
  circle C6 centre (3.81, -11.83) radius 0.6
  point P18 (3.81, -11.98)
  point P19 (3.81, -11.68)
  point P21 (3.96, -11.83)
  point P20 (3.66, -11.83)
  point P26 (3.81, -11.83)
  vertical L9
  horizontal L10
  symmetric L10 L11 L12
  symmetric L9 L13 L14
  coincident P18 L11
  coincident P19 L12
  coincident P21 L13
  coincident P20 L14
  midpoint L10 P26
  dimension "d55" diameter C5 = 1
  dimension "d56" = 0.1
extrude "Extrude3" cut sketch "Sketch2" profile of L11 L12 L13 L14 C5 C6 against normal blind 2
extrude "Extrude4" new body sketch "Sketch2" profile of C5 C6 to an object bodies "ring5"
rectangular_pattern "R-Pattern1" uSpaceDistance 2.54 vSpaceDistance 0
rectangular_pattern "R-Pattern2" uSpaceDistance 2.54 vSpaceDistance 0 bodies "ring6", "ring7 (1)", "ring7"
work_plane "WorkPlane1" AlongDistance -0.1
sketch "Sketch1" plane through (3.81, 11.83, 2.4) normal (0, 0, 1) x axis (1, 0, 0)
  line L1 (0.25, 0.25) -> (-0.25, 0.25)
  line L2 (0.25, -0.25) -> (0.25, 0.25)
  line L3 (-0.25, -0.25) -> (0.25, -0.25)
  line L4 (-0.25, 0.25) -> (-0.25, -0.25)
  point P2 (-0.25, 0.25)
  point P6 (-0.25, 0.25)
  point P4 (0.25, -0.25)
  point P7 (0.25, -0.25)
  horizontal L1
  vertical L2
  horizontal L3
  vertical L4
  coincident P2 P6
  coincident P4 P7
sketch "Sketch2" plane through (0, 0, 1.5) normal (0, 0, 1) x axis (-1, 0, 0)
  line L1 (7.3, 13.1) -> (12.7, 13.1)
  line L2 (7.3, 11.6) -> (7.3, 13.1)
  line L3 (-6.3, 10.6) -> (6.3, 10.6)
  line L4 (-7.3, 13.1) -> (-7.3, 11.6)
  line L5 (-12.7, 13.1) -> (-7.3, 13.1)
  line L6 (-12.7, -13.1) -> (-12.7, 13.1)
  line L7 (12.7, -13.1) -> (-12.7, -13.1)
  line L8 (12.7, 13.1) -> (12.7, -13.1)
  circle C1 centre (-3.81, -11.83) radius 0.6
  circle C2 centre (-1.27, -11.83) radius 0.6
  circle C3 centre (1.27, -11.83) radius 0.6
  circle C4 centre (3.81, -11.83) radius 0.6
  circle C5 centre (10.7, -11.1) radius 1.5
  circle C6 centre (-10.7, -11.1) radius 1.5
  circle C7 centre (10.7, 11.1) radius 1.5
  circle C8 centre (-10.7, 11.1) radius 1.5
  arc A1 centre (6.3, 11.6) radius 1 clockwise from (7.3, 11.6) to (6.3, 10.6)
  arc A2 centre (-6.3, 11.6) radius 1 clockwise from (-6.3, 10.6) to (-7.3, 11.6)
  circle C9 centre (-3.81, -11.83) radius 1
  concentric C1 C9
  dimension "d70" diameter C9 = 2
loft "Loft1" sketch "Sketch2" + "Sketch1" bodies "solder1"
rectangular_pattern "R-Pattern1" uSpaceDistance -2.54 vSpaceDistance 0 bodies "solder2", "solder3", "solder4"
derived_base_feature "Derived Base Feature1" bodies "side1", "side2", "Body1"
as_built_joint "As-built2"
as_built_joint "As-built3"
as_built_joint "As-built4"
joint "Assemble3" alignAngle 0 alignOffsetX 10.775 (= "( 25.4 / 2 ) * 1 mm - ( 0.85 / 2 ) * 1 mm - 1.5 mm") alignOffsetY -1.3 (= "( -26.2 / 2 ) * 1 mm + ( 1.6 / 2 ) * 1 mm + 11 mm") alignOffsetZ 0
derived_base_feature "Derived Base Feature1" bodies "side1", "side2", "Body1"
position "Position4"
joint_origin "JointOrigin1"
position "Position5"
as_built_joint "As-built5"
derived_base_feature "Derived Base Feature1" bodies "side1", "side2", "Body1"
joint "Assemble4" alignAngle 0 alignOffsetX 7.775 (= "( 25.4 / 2 ) * 1 mm - ( 0.85 / 2 ) * 1 mm - 3 mm - 1.5 mm") alignOffsetY -1.3 alignOffsetZ 0
base_feature "Base Feature1"
sketch "Sketch1" plane through (0, 0, 0) normal (0, 0, 1) x axis (1, 0, 0)
  line L1 (-0.425, -0.775) -> (0.425, -0.775)
  line L2 (-0.425, 0.775) -> (-0.425, -0.775)
  line L3 (0.425, 0.775) -> (-0.425, 0.775)
  line L4 (0.425, -0.775) -> (0.425, 0.775)
  line L5 (-0.425, 0) -> (0.425, 0)
  line L6 (-0.425, -0.625) -> (0.425, -0.625)
  line L7 (-0.425, 0.625) -> (0.425, 0.625)
  line L8 (0, -0.625) -> (0, 0.625)
  point P6 (0.425, 0)
  point P7 (-0.425, 0)
  point P8 (0.425, -0.625)
  point P9 (-0.425, -0.625)
  point P10 (0.425, 0.625)
  point P11 (-0.425, 0.625)
  point P12 (0, 0.625)
  point P13 (0, -0.625)
  point P1 (0, 0)
  point P2 (0.425, -0.775)
  point P3 (-0.425, -0.775)
  point P5 (0.425, 0.775)
  horizontal L1
  vertical L2
  horizontal L3
  vertical L4
  midpoint L4 P6
  midpoint L2 P7
  coincident L4 P8
  coincident L2 P9
  perpendicular L2 L6
  coincident L4 P10
  coincident L2 P11
  perpendicular L2 L7
  midpoint L7 P12
  midpoint L6 P13
  coincident P1 L5
  coincident P1 L8
  dimension "d117_1" distance P2 P3 = 0.85
  dimension "d118_1" distance P2 P5 = 1.55
  dimension "d120_1" distance L1 L6 = 0.15
  dimension "d121_1" distance L3 L7 = 0.15
extrude "Extrude1" new body sketch "Sketch1" profile of L2 L4 L6 L7 blind 0.45 named "d123_1"
extrude "Extrude2" new body sketch "Sketch1" profile of L1 L2 L3 L4 L6 L7 blind 0.45 named "d125_1" bodies "side1", "side2"
sketch "Sketch2" plane through (0, 0, 0.45) normal (0, 0, 1) x axis (1, 0, 0)
  dimension "d127_1" = 0.5
extrude "Extrude3" add sketch "Sketch2" blind 0.01 named "d128_1"
joint "Assemble5" alignAngle 0 alignOffsetX 6.275 (= "( 25.4 / 2 ) * 1 mm - ( 0.85 / 2 ) * 1 mm - 3 mm - 1.5 mm - 1.5 mm") alignOffsetY -1.3 alignOffsetZ 0
rectangular_pattern "⨁" uSpaceDistance -1.5 vSpaceDistance 0
as_built_joint "As-built6"
as_built_joint "As-built7"
base_feature "Base Feature1"
sketch "Sketch1" plane through (0, 0, 0) normal (0, 0, 1) x axis (1, 0, 0)
  line L1 (-0.625, -0.85) -> (0.625, -0.85)
  line L2 (-0.625, 0.85) -> (-0.625, -0.85)
  line L3 (0.625, 0.85) -> (-0.625, 0.85)
  line L4 (0.625, -0.85) -> (0.625, 0.85)
  line L5 (-0.625, 0) -> (0.625, 0)
  line L6 (0, 0.85) -> (0, -0.85)
  point P6 (0.625, 0)
  point P7 (-0.625, 0)
  point P8 (0, -0.85)
  point P9 (0, 0.85)
  point P1 (0, 0)
  point P2 (0.625, -0.85)
  point P3 (-0.625, -0.85)
  point P5 (0.625, 0.85)
  horizontal L1
  vertical L2
  horizontal L3
  vertical L4
  midpoint L4 P6
  midpoint L2 P7
  midpoint L1 P8
  midpoint L3 P9
  coincident P1 L5
  coincident P1 L6
  dimension "d134" distance P2 P3 = 1.25
  dimension "d135" distance P2 P5 = 1.7
extrude "Extrude1" new body sketch "Sketch1" profile of L1 L2 L3 L4 along normal blind 0.8
sketch "Sketch2" plane through (0, 0, 0.8) normal (0, 0, 1) x axis (1, 0, 0)
  line L1 (-0.625, 0.85) -> (0.625, 0.85)
  line L2 (-0.625, -0.85) -> (-0.625, 0.85)
  line L3 (0.625, -0.85) -> (-0.625, -0.85)
  line L4 (0.625, 0.85) -> (0.625, -0.85)
  line L5 (0, 0.85) -> (0, -0.85)
  curve K1
  curve K2
  curve K3
  curve K4
  line L6 (0.625, 0) -> (-0.625, 0)
  point P7 (0, 0.85)
  point P6 (0, -0.85)
  point P8 (-0.625, 0)
  point P9 (0.625, 0)
  perpendicular L1 L5
  coincident L1 P7
  coincident L3 P6
  midpoint L2 P8
  midpoint L4 P9
  dimension "d142" distance L5 K3 = 0.3
  dimension "d143" distance L5 K1 = 0.3
  dimension "d146" distance K4 L6 = 0.5
  dimension "d141" Text1-Height = 0.4
  dimension "d145" distance = 1
extrude "Extrude2" add sketch "Sketch2" blind 0.01
sketch "Sketch3" plane through (0, -0.85, 0) normal (0, -1, 0) x axis (-1, 0, 0)
  line L1 (-0.625, 0) -> (0.625, 0)
  line L2 (-0.625, -0.8) -> (-0.625, 0)
  line L3 (0.625, -0.8) -> (-0.625, -0.8)
  line L4 (0.625, 0) -> (0.625, -0.8)
  line L5 (-0.635, 0) -> (-0.625, 0)
  line L6 (-0.635, -0.81) -> (-0.635, 0)
  line L7 (0.635, -0.81) -> (-0.635, -0.81)
  line L8 (0.635, 0) -> (0.635, -0.81)
  line L9 (0.625, 0) -> (0.635, 0)
  line L10 (-0.625, -0.8) -> (0.625, -0.8)
  line L11 (-0.625, -0.8) -> (-0.625, 0)
  point P3 (-0.625, 0)
  point P6 (-0.625, 0)
  point P2 (0.625, 0)
  point P11 (0.625, 0)
  point P5 (0.625, -0.8)
  point P12 (0.625, -0.8)
  point P4 (-0.625, -0.8)
  point P13 (-0.625, -0.8)
  point P7 (-0.635, 0)
  coincident P3 P6
  horizontal L5
  perpendicular L5 L6
  perpendicular L6 L7
  perpendicular L7 L8
  coincident P2 P11
  perpendicular L4 L9
  coincident P5 P12
  coincident P4 P13
  dimension "d149" distance P6 P7 = 0.01
  dimension "d150" distance L7 L10 = 0.01
  dimension "d151" distance L4 L8 = 0.01
extrude "Extrude3" add sketch "Sketch3" profile of L2 L3 L4 L5 L6 L7 L8 L9 L10 L11 blind -0.05 from offset -0.25
work_plane "WorkPlane1" AlongDistance 0.4 named "d4_1"
sketch "Sketch5" plane through (0, -1.25, 0.4) normal (0, -1, 0) x axis (1, 0, 0)
  line L1 (0, -0.4) -> (0, 0.41)
  line L2 (-0.635, -0.4) -> (-0.635, 0.41)
  line L3 (0.635, 0.41) -> (0.635, -0.4)
  line L4 (-0.635, 0.41) -> (0.635, 0.41)
  line L5 (-0.625, -0.4) -> (0.625, -0.4)
  line L6 (-0.15, -0.59) -> (0.15, -0.59)
  line L7 (-0.15, -0.49) -> (-0.15, -0.59)
  line L8 (0.15, -0.49) -> (-0.15, -0.49)
  line L9 (0.15, -0.59) -> (0.15, -0.49)
  line L10 (-0.15, -0.49) -> (0.15, -0.59)
  line L11 (0.15, -0.49) -> (-0.15, -0.59)
  point P2 (0, 0.41)
  point P3 (0, -0.4)
  point P14 (0, -0.54)
  point P12 (-0.15, -0.49)
  point P13 (0.15, -0.49)
  point P11 (-0.15, -0.59)
  vertical L1
  symmetric L1 L2 L3
  coincident P2 L4
  coincident P3 L5
  horizontal L6
  perpendicular L6 L7
  parallel L6 L8
  parallel L7 L9
  coincident L10 P14
  coincident L11 P14
  coincident L1 P14
  dimension "d6_1" distance P12 P13 = 0.3
  dimension "d7_1" distance P11 P12 = 0.1
  dimension "d8_1" distance L4 L6 = 1
sketch "Sketch7" plane through (0, -0.85, 0) normal (0, -1, 0) x axis (1, 0, 0)
  line L1 (0.625, 0) -> (-0.625, 0)
  line L2 (0.625, 0.8) -> (0.625, 0)
  line L3 (-0.625, 0.8) -> (0.625, 0.8)
  line L4 (-0.625, 0) -> (-0.625, 0.8)
  line L5 (-0.15, 0.3) -> (0.15, 0.3)
  line L6 (-0.15, 0.4) -> (-0.15, 0.3)
  line L7 (0.15, 0.4) -> (-0.15, 0.4)
  line L8 (0.15, 0.3) -> (0.15, 0.4)
  line L9 (-0.15, 0.4) -> (0.15, 0.3)
  line L10 (0.15, 0.4) -> (-0.15, 0.3)
  line L11 (0, 0) -> (0, 0.81)
  line L12 (-0.625, 0) -> (0.625, 0)
  point P10 (0, 0.35)
  point P8 (-0.15, 0.4)
  point P9 (0.15, 0.4)
  point P7 (-0.15, 0.3)
  horizontal L5
  perpendicular L5 L6
  parallel L5 L7
  parallel L6 L8
  coincident L9 P10
  coincident L10 P10
  coincident P10 L11
  dimension "d9_1" distance P8 P9 = 0.3
  dimension "d10_1" distance P7 P8 = 0.1
  dimension "d11_1" distance L7 L12 = 0.4
work_plane "WorkPlane6"
sketch "Sketch10" plane through (0, -1.25, -0.14) normal (1, 0, 0) x axis (0, 1, 0)
  line L1 (0, 0.05) -> (0, -0.05)
  line L2 (0.0328, 0) -> (0, 0)
  line L3 (0.2746, 0.4278) -> (0.1254, 0.0622)
  line L4 (0.4, 0.49) -> (0.3672, 0.49)
  arc A1 centre (0.0328, 0.1) radius 0.1 clockwise from (0.1254, 0.0622) to (0.0328, 0)
  arc A2 centre (0.3672, 0.39) radius 0.1 clockwise from (0.2746, 0.4278) to (0.3672, 0.49)
  point P2 (0, 0)
  point P6 (0, 0)
  point P9 (0.4, 0.49)
  point P10 (0.4, 0.49)
  point P7 (0.1, 0)
  point P8 (0.3, 0.49)
  coincident P2 P6
  perpendicular L1 L2
  horizontal L4
  coincident P9 P10
  coincident P7 L2
  coincident P7 L3
  tangent L2 A1
  tangent L3 A1
  coincident P8 L3
  coincident P8 L4
  tangent L3 A2
  tangent L4 A2
  equal A1 A2
  dimension "d24_1" distance P6 P7 = 0.1
  dimension "d25_1" distance P8 P9 = 0.1
  dimension "d26_1" radius A1 = 0.1
loft "Loft1" sketch "Sketch5" + "Sketch7" bodies "leg1"
work_plane "WorkPlane7"
mirror "Mirror1" mirrorStitchTolerance 0.1 named "d28_1" bodies "leg2"
joint "Assemble6" alignAngle 0 alignOffsetX 1.375 (= "( 25.4 / 2 ) * 1 mm - ( 1.25 / 2 ) * 1 mm - 10.7 mm") alignOffsetY -1.3 alignOffsetZ 0.19
derived_base_feature "Derived Base Feature1" bodies "side1", "side2", "Body1"
position "Position6"
joint_origin "JointOrigin1"
joint "Assemble7" alignAngle 0 alignOffsetX -0.225 (= "( 25.4 / 2 ) * 1 mm - ( 0.85 / 2 ) * 1 mm - 12.5 mm") alignOffsetY -1.3 alignOffsetZ 0
derived_base_feature "Derived Base Feature1" bodies "side1", "side2", "Body1"
position "Position7"
joint_origin "JointOrigin1"
position "Position8"
as_built_joint "As-built8"
derived_base_feature "Derived Base Feature1" bodies "side1", "side2", "Body1"
position "Position9"
joint_origin "JointOrigin1"
derived_base_feature "Derived Base Feature1" bodies "side1", "side2", "Body1"
position "Position10"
